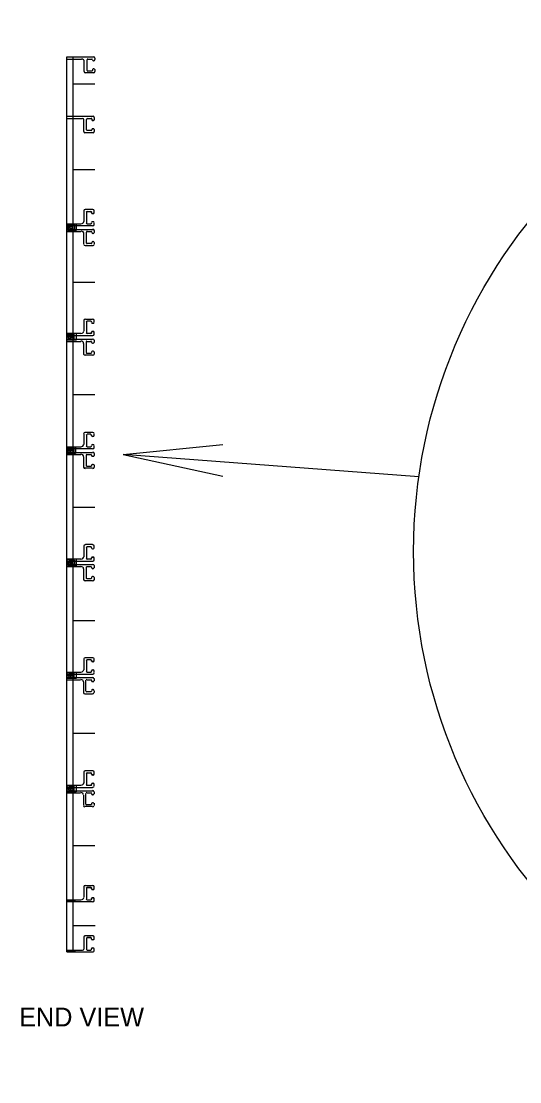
# Model space of a CAD drawing. Extents: x 647822 to 649292, y 298458 to 299646.
# Drawn here: x 648961.1 to 649074.6, y 299016.3 to 299257.7 of the extents above; entities that cross this region are included whole.
import ezdxf

# ---------------------------------------------------------------- set-up
doc = ezdxf.new("R2010")
doc.units = 0
doc.layers.add('2', color=7, linetype='Continuous')

msp = doc.modelspace()

# ---------------------------------------------------------------- linework, layer by layer
at = {"layer": '2'}
for p, q in [((648971.47, 299045.89), (648971.47, 299249.56)), ((648971.47, 299249.56), (648977.58, 299249.56)), ((648972.97, 299045.89), (648972.97, 299249.56)), ((648977.84, 299249.3), (648977.84, 299248.95)), ((648971.47, 299249.06), (648974.84, 299249.06)), ((648975.47, 299246.2), (648975.47, 299248.56)), ((648976.09, 299246.47), (648976.09, 299248.9)), ((648976.25, 299249.06), (648977.18, 299249.06)), ((648977.34, 299248.9), (648977.34, 299248.85)), ((648977.34, 299246.67), (648977.34, 299246.47)), ((648977.5, 299248.69), (648977.58, 299248.69)), ((648977.68, 299246.83), (648977.5, 299246.83)), ((648977.59, 299248.69), (648977.59, 299248.69)), ((648977.84, 299246.67), (648977.84, 299246.2)), ((648977.58, 299245.94), (648975.73, 299245.94)), ((648977.18, 299246.31), (648976.25, 299246.31)), ((648972.97, 299243.44), (648977.84, 299243.44)), ((648971.47, 299236.06), (648977.46, 299236.06)), ((648971.47, 299235.56), (648975.08, 299235.56)), ((648975.34, 299232.57), (648975.34, 299235.3)), ((648975.97, 299232.97), (648975.97, 299235.3)), ((648976.23, 299235.56), (648977.06, 299235.56)), ((648977.22, 299235.4), (648977.22, 299235.21)), ((648977.56, 299235.05), (648977.38, 299235.05)), ((648977.72, 299235.8), (648977.72, 299235.21)), ((648977.46, 299232.31), (648975.6, 299232.31)), ((648977.06, 299232.81), (648976.13, 299232.81)), ((648977.22, 299233.04), (648977.22, 299232.97)), ((648977.56, 299233.2), (648977.38, 299233.2)), ((648977.72, 299233.04), (648977.72, 299232.57)), ((648972.97, 299223.94), (648977.84, 299223.94)), ((648975.34, 299214.56), (648975.34, 299212.06)), ((648977.34, 299214.81), (648975.72, 299214.81)), ((648975.97, 299214.19), (648975.97, 299211.69)), ((648976.97, 299214.31), (648976.09, 299214.31)), ((648977.09, 299214.06), (648977.09, 299214.19)), ((648977.47, 299213.94), (648977.34, 299213.94)), ((648977.72, 299214.06), (648977.72, 299214.56)), ((648971.47, 299211.56), (648974.72, 299211.56)), ((648971.47, 299211.19), (648977.34, 299211.19)), ((648976.09, 299211.56), (648976.97, 299211.56)), ((648977.09, 299211.69), (648977.09, 299211.81)), ((648977.34, 299212.06), (648977.47, 299212.06)), ((648977.72, 299211.44), (648977.72, 299211.81)), ((648971.47, 299210.31), (648977.47, 299210.31)), ((648971.47, 299209.81), (648974.72, 299209.81)), ((648975.34, 299206.94), (648975.34, 299209.31)), ((648975.97, 299207.19), (648975.97, 299209.69)), ((648976.09, 299209.81), (648976.97, 299209.81)), ((648977.22, 299209.69), (648977.22, 299209.56)), ((648977.47, 299209.44), (648977.47, 299209.44)), ((648977.72, 299210.06), (648977.72, 299209.56)), ((648977.47, 299206.56), (648975.72, 299206.56)), ((648976.97, 299207.06), (648976.09, 299207.06)), ((648977.22, 299207.31), (648977.22, 299207.19)), ((648977.47, 299207.56), (648977.47, 299207.56)), ((648977.72, 299207.31), (648977.72, 299206.94)), ((648972.97, 299198.31), (648977.84, 299198.31)), ((648975.34, 299189.56), (648975.34, 299187.19)), ((648977.34, 299189.81), (648975.72, 299189.81)), ((648975.97, 299189.31), (648975.97, 299186.81)), ((648976.97, 299189.44), (648976.09, 299189.44)), ((648977.09, 299189.19), (648977.09, 299189.31)), ((648977.47, 299188.94), (648977.34, 299188.94)), ((648977.72, 299189.19), (648977.72, 299189.56)), ((648971.47, 299186.69), (648974.72, 299186.69)), ((648976.09, 299186.69), (648976.97, 299186.69)), ((648977.09, 299186.81), (648977.09, 299186.94)), ((648977.34, 299187.06), (648977.47, 299187.06)), ((648977.72, 299186.44), (648977.72, 299186.94)), ((648971.47, 299186.19), (648977.34, 299186.19)), ((648971.47, 299185.31), (648977.34, 299185.31)), ((648971.47, 299184.81), (648974.72, 299184.81)), ((648975.34, 299181.94), (648975.34, 299184.31)), ((648975.97, 299182.31), (648975.97, 299184.69)), ((648976.09, 299184.81), (648976.97, 299184.81)), ((648977.09, 299184.69), (648977.09, 299184.56)), ((648977.34, 299184.44), (648977.47, 299184.44)), ((648977.72, 299185.06), (648977.72, 299184.56)), ((648977.34, 299181.69), (648975.59, 299181.69)), ((648976.97, 299182.06), (648976.09, 299182.06)), ((648977.09, 299182.44), (648977.09, 299182.31)), ((648977.47, 299182.56), (648977.34, 299182.56)), ((648977.72, 299182.44), (648977.72, 299181.94)), ((648972.97, 299172.69), (648977.84, 299172.69)), ((648975.34, 299163.81), (648975.34, 299161.31)), ((648977.34, 299164.06), (648975.59, 299164.06)), ((648975.97, 299163.44), (648975.97, 299160.94)), ((648976.97, 299163.69), (648976.09, 299163.69)), ((648977.09, 299163.31), (648977.09, 299163.44)), ((648977.47, 299163.19), (648977.34, 299163.19)), ((648977.72, 299163.31), (648977.72, 299163.81)), ((648971.47, 299160.81), (648974.72, 299160.81)), ((648971.47, 299160.44), (648977.34, 299160.44)), ((648976.09, 299160.81), (648976.97, 299160.81)), ((648977.09, 299160.94), (648977.09, 299161.06)), ((648977.34, 299161.31), (648977.47, 299161.31)), ((648977.72, 299160.69), (648977.72, 299161.06)), ((648984.35, 299159.1), (649007, 299161.31)), ((648971.47, 299159.56), (648977.34, 299159.56)), ((648971.47, 299159.06), (648974.72, 299159.06)), ((648975.34, 299156.19), (648975.34, 299158.56)), ((648975.97, 299156.44), (648975.97, 299158.94)), ((648976.09, 299159.06), (648976.97, 299159.06)), ((648977.09, 299158.94), (648977.09, 299158.81)), ((648977.34, 299158.69), (648977.47, 299158.69)), ((648977.72, 299159.31), (648977.72, 299158.81)), ((649051.64, 299154.02), (648984.35, 299159.1)), ((648984.35, 299159.1), (649007, 299154.13)), ((648977.34, 299155.94), (648975.59, 299155.94)), ((648976.97, 299156.31), (648976.09, 299156.31)), ((648977.09, 299156.69), (648977.09, 299156.44)), ((648977.47, 299156.81), (648977.34, 299156.81)), ((648977.72, 299156.69), (648977.72, 299156.19)), ((648972.97, 299147.06), (648977.84, 299147.06)), ((648975.34, 299138.19), (648975.34, 299135.81)), ((648977.34, 299138.56), (648975.72, 299138.56)), ((648976.97, 299138.06), (648976.09, 299138.06)), ((648977.72, 299137.81), (648977.72, 299138.19)), ((648975.97, 299137.94), (648975.97, 299135.44)), ((648977.09, 299137.81), (648977.09, 299137.94)), ((648977.47, 299137.56), (648977.34, 299137.56)), ((648977.34, 299135.69), (648977.47, 299135.69)), ((648971.47, 299135.31), (648974.72, 299135.31)), ((648971.47, 299134.81), (648977.34, 299134.81)), ((648971.47, 299134.06), (648977.34, 299134.06)), ((648971.47, 299133.56), (648974.72, 299133.56)), ((648975.97, 299130.94), (648975.97, 299133.44)), ((648976.09, 299135.31), (648976.97, 299135.31)), ((648976.09, 299133.56), (648976.97, 299133.56)), ((648977.09, 299135.44), (648977.09, 299135.56)), ((648977.09, 299133.44), (648977.09, 299133.31)), ((648977.72, 299135.06), (648977.72, 299135.56)), ((648977.72, 299133.81), (648977.72, 299133.31)), ((648975.34, 299130.56), (648975.34, 299133.06)), ((648976.97, 299130.81), (648976.09, 299130.81)), ((648977.09, 299131.06), (648977.09, 299130.94)), ((648977.34, 299133.06), (648977.47, 299133.06)), ((648977.47, 299131.31), (648977.34, 299131.31)), ((648977.72, 299131.06), (648977.72, 299130.56)), ((648977.34, 299130.31), (648975.59, 299130.31)), ((648972.97, 299121.31), (648977.84, 299121.31)), ((648975.34, 299112.56), (648975.34, 299110.06)), ((648977.34, 299112.81), (648975.72, 299112.81)), ((648975.97, 299112.19), (648975.97, 299109.69)), ((648976.97, 299112.31), (648976.09, 299112.31)), ((648977.09, 299112.06), (648977.09, 299112.19)), ((648977.47, 299111.94), (648977.34, 299111.94)), ((648977.72, 299112.06), (648977.72, 299112.56)), ((648971.47, 299109.56), (648974.72, 299109.56)), ((648976.09, 299109.56), (648976.97, 299109.56)), ((648977.09, 299109.69), (648977.09, 299109.81)), ((648977.34, 299110.06), (648977.47, 299110.06)), ((648977.72, 299109.44), (648977.72, 299109.81)), ((648971.47, 299109.06), (648977.34, 299109.06)), ((648971.47, 299108.31), (648977.34, 299108.31)), ((648971.47, 299107.81), (648974.59, 299107.81)), ((648975.34, 299104.94), (648975.34, 299107.31)), ((648975.84, 299105.19), (648975.84, 299107.69)), ((648976.09, 299107.81), (648976.97, 299107.81)), ((648977.09, 299107.69), (648977.09, 299107.56)), ((648977.34, 299107.44), (648977.47, 299107.44)), ((648977.72, 299108.06), (648977.72, 299107.56)), ((648977.34, 299104.56), (648975.59, 299104.56)), ((648976.97, 299105.06), (648976.09, 299105.06)), ((648977.09, 299105.31), (648977.09, 299105.19)), ((648977.47, 299105.56), (648977.34, 299105.56)), ((648977.72, 299105.31), (648977.72, 299104.94)), ((648972.97, 299095.69), (648977.84, 299095.69)), ((648975.34, 299086.81), (648975.34, 299084.31)), ((648977.34, 299087.06), (648975.72, 299087.06)), ((648975.97, 299086.44), (648975.97, 299083.94)), ((648976.97, 299086.56), (648976.09, 299086.56)), ((648977.09, 299086.31), (648977.09, 299086.44)), ((648977.47, 299086.19), (648977.34, 299086.19)), ((648977.72, 299086.31), (648977.72, 299086.81)), ((648971.47, 299083.81), (648974.72, 299083.81)), ((648971.47, 299083.31), (648977.34, 299083.31)), ((648971.47, 299082.56), (648977.34, 299082.56)), ((648976.09, 299083.81), (648976.97, 299083.81)), ((648977.09, 299083.94), (648977.09, 299084.06)), ((648977.34, 299084.31), (648977.47, 299084.31)), ((648977.72, 299083.69), (648977.72, 299084.06)), ((648971.47, 299082.06), (648974.59, 299082.06)), ((648975.34, 299079.19), (648975.34, 299081.56)), ((648975.84, 299079.44), (648975.84, 299081.94)), ((648976.09, 299082.06), (648976.97, 299082.06)), ((648977.09, 299081.94), (648977.09, 299081.81)), ((648977.34, 299081.69), (648977.47, 299081.69)), ((648977.72, 299082.31), (648977.72, 299081.81)), ((648977.34, 299078.94), (648975.59, 299078.94)), ((648976.97, 299079.31), (648976.09, 299079.31)), ((648977.09, 299079.69), (648977.09, 299079.44)), ((648977.47, 299079.81), (648977.34, 299079.81)), ((648977.72, 299079.69), (648977.72, 299079.19)), ((648972.97, 299070.06), (648977.84, 299070.06)), ((648977.34, 299060.94), (648975.72, 299060.94)), ((648975.34, 299060.69), (648975.34, 299058.31)), ((648975.97, 299060.31), (648975.97, 299057.94)), ((648976.97, 299060.56), (648976.09, 299060.56)), ((648976.09, 299060.56), (648976.97, 299060.56)), ((648977.09, 299060.19), (648977.09, 299060.31)), ((648977.47, 299060.06), (648977.34, 299060.06)), ((648977.72, 299060.19), (648977.72, 299060.69)), ((648971.47, 299057.69), (648974.72, 299057.69)), ((648971.47, 299057.31), (648977.34, 299057.31)), ((648976.09, 299057.69), (648976.97, 299057.69)), ((648977.09, 299057.94), (648977.09, 299058.06)), ((648977.34, 299058.19), (648977.47, 299058.19)), ((648977.72, 299057.56), (648977.72, 299058.06)), ((648972.97, 299051.85), (648977.94, 299051.85)), ((648975.34, 299049.26), (648975.34, 299046.53)), ((648977.46, 299049.52), (648975.6, 299049.52)), ((648975.97, 299048.98), (648975.97, 299046.43)), ((648976.09, 299049.14), (648976.93, 299049.14)), ((648976.97, 299049.14), (648976.13, 299049.14)), ((648977.09, 299048.8), (648977.09, 299048.98)), ((648977.72, 299048.8), (648977.72, 299049.26)), ((648977.09, 299046.43), (648977.09, 299046.61)), ((648977.56, 299048.64), (648977.25, 299048.64)), ((648977.25, 299046.77), (648977.56, 299046.77)), ((648977.72, 299046.15), (648977.72, 299046.61)), ((648971.47, 299046.27), (648975.08, 299046.27)), ((648971.47, 299045.89), (648977.46, 299045.89)), ((648976.13, 299046.27), (648976.93, 299046.27))]:
    msp.add_line(p, q, dxfattribs=at)
for points in [[(648973.59, 299211.44), (648973.59, 299210.06), (648971.72, 299210.06), (648971.59, 299211.44), (648973.09, 299211.19), (648973.22, 299211.31), (648973.22, 299210.31), (648971.97, 299210.31), (648971.97, 299210.94), (648972.72, 299211.06), (648972.84, 299210.56), (648972.22, 299210.56), (648972.22, 299211.44), (648973.09, 299211.44), (648973.09, 299211.19)], [(648973.59, 299186.44), (648973.59, 299185.06), (648971.59, 299185.06), (648971.59, 299186.44), (648973.09, 299186.19), (648973.09, 299186.31), (648973.09, 299185.31), (648971.97, 299185.44), (648971.84, 299186.06), (648972.72, 299186.06), (648972.84, 299185.69), (648972.22, 299185.69), (648972.22, 299186.44), (648973.09, 299186.44), (648973.09, 299186.31)], [(648973.47, 299160.69), (648973.47, 299159.31), (648971.59, 299159.31), (648971.59, 299160.69), (648973.09, 299160.44), (648973.09, 299160.56), (648973.09, 299159.56), (648971.84, 299159.69), (648971.84, 299160.19), (648972.72, 299160.31), (648972.72, 299159.94), (648972.09, 299159.94), (648972.09, 299160.69), (648973.09, 299160.69), (648973.09, 299160.56)], [(648973.59, 299135.19), (648973.59, 299133.69), (648971.72, 299133.81), (648971.59, 299135.19), (648973.09, 299134.94), (648973.22, 299135.06), (648973.22, 299134.06), (648971.97, 299134.06), (648971.97, 299134.69), (648972.72, 299134.69), (648972.84, 299134.31), (648972.22, 299134.31), (648972.22, 299135.19), (648973.09, 299135.19), (648973.09, 299134.94)], [(648973.59, 299109.44), (648973.59, 299108.06), (648971.59, 299108.06), (648971.59, 299109.44), (648973.09, 299109.19), (648973.09, 299109.31), (648973.09, 299108.31), (648971.97, 299108.44), (648971.84, 299108.94), (648972.72, 299109.06), (648972.84, 299108.69), (648972.22, 299108.69), (648972.22, 299109.44), (648973.09, 299109.44), (648973.09, 299109.31)], [(648973.59, 299083.69), (648973.59, 299082.31), (648971.59, 299082.31), (648971.59, 299083.69), (648973.09, 299083.44), (648973.09, 299083.56), (648973.09, 299082.56), (648971.97, 299082.69), (648971.84, 299083.19), (648972.72, 299083.31), (648972.84, 299082.94), (648972.22, 299082.94), (648972.22, 299083.69), (648973.09, 299083.69), (648973.09, 299083.44)], [(648971.47, 299057.56), (648972.84, 299057.56), (648973.34, 299057.56), (648973.34, 299057.44), (648971.59, 299057.44)], [(648971.47, 299046.14), (648972.84, 299046.14), (648973.34, 299046.14), (648973.34, 299046.02), (648971.59, 299046.02)]]:
    msp.add_lwpolyline(points, dxfattribs=at)
msp.add_circle((649171.11, 299137), 120.68, dxfattribs=at)
for centre, radius, start, end in [((648977.58, 299249.3), 0.26, 0, 90), ((648976.25, 299248.9), 0.16, 90, 180), ((648977.18, 299248.9), 0.16, 0, 90), ((648977.5, 299248.85), 0.16, 180, 270), ((648977.5, 299246.67), 0.16, 90, 180), ((648977.58, 299248.95), 0.26, 270, 0), ((648977.68, 299246.67), 0.16, 0, 90), ((648975.73, 299246.2), 0.26, 180, 270), ((648976.25, 299246.47), 0.16, 180, 270), ((648977.18, 299246.47), 0.16, 270, 0), ((648977.58, 299246.2), 0.26, 270, 0), ((648975.08, 299235.3), 0.26, 0, 90), ((648976.23, 299235.3), 0.26, 90, 180), ((648977.06, 299235.4), 0.16, 0, 90), ((648977.38, 299235.21), 0.16, 180, 270), ((648977.46, 299235.8), 0.26, 0, 90), ((648977.56, 299235.21), 0.16, 270, 0), ((648975.6, 299232.57), 0.26, 180, 270), ((648976.13, 299232.97), 0.16, 180, 270), ((648977.06, 299232.97), 0.16, 270, 0), ((648977.38, 299233.04), 0.16, 90, 180), ((648977.46, 299232.57), 0.26, 270, 0), ((648977.56, 299233.04), 0.16, 0, 90), ((648975.6, 299049.26), 0.26, 90, 180), ((648976.13, 299048.98), 0.16, 90, 180), ((648976.93, 299048.98), 0.16, 0, 90), ((648977.25, 299048.8), 0.16, 180, 270), ((648977.46, 299049.26), 0.26, 0, 90), ((648977.56, 299048.8), 0.16, 270, 0), ((648975.08, 299046.53), 0.26, 270, 0), ((648976.13, 299046.43), 0.16, 180, 270), ((648976.93, 299046.43), 0.16, 270, 0), ((648977.25, 299046.61), 0.16, 90, 180), ((648977.56, 299046.61), 0.16, 0, 90), ((648977.46, 299046.15), 0.26, 270, 0)]:
    msp.add_arc(centre, radius, start, end, dxfattribs=at)
for centre, major_axis, start_param, end_param in [((648974.82, 299248.54), (0.653, 0), 0, 1.570796), ((648975.68, 299214.55), (-0.327, 0), 4.712389, 6.283185), ((648976.09, 299214.22), (-0.163, 0), 4.712389, 6.283185), ((648976.99, 299214.22), (-0.163, 0), 3.141593, 4.712389), ((648977.4, 299214.09), (0.251, 0), 3.141593, 4.712389), ((648977.4, 299214.55), (0.327, 0), 0, 1.570796), ((648977.48, 299214.09), (0.251, 0), 4.712389, 6.283185), ((648974.7, 299212.11), (0.653, 0), 4.712389, 6.283185), ((648976.09, 299211.71), (0.163, 0), 3.141593, 4.712389), ((648976.99, 299211.71), (0.163, 0), 4.712389, 6.283185), ((648977.4, 299211.84), (-0.251, 0), 4.712389, 6.283185), ((648977.4, 299211.39), (0.327, 0), 4.712389, 6.283185), ((648977.48, 299211.84), (0.251, 0), 0, 1.570796), ((648974.73, 299209.34), (0.653, 0), 0, 1.570796), ((648976.11, 299209.73), (-0.163, 0), 4.712389, 6.283185), ((648977.01, 299209.73), (0.163, 0), 0, 1.570796), ((648977.43, 299209.6), (-0.251, 0), 0, 1.570796), ((648977.43, 299210.06), (0.327, 0), 0, 1.570796), ((648977.5, 299209.6), (0.251, 0), 4.712389, 6.283185), ((648975.7, 299206.89), (0.327, 0), 3.141593, 4.712389), ((648976.11, 299207.22), (-0.163, 0), 0, 1.570796), ((648977.01, 299207.22), (0.163, 0), 4.712389, 6.283185), ((648977.43, 299207.35), (-0.251, 0), 4.712389, 6.283185), ((648977.43, 299206.89), (0.327, 0), 4.712389, 6.283185), ((648977.5, 299207.35), (-0.251, 0), 3.141593, 4.712389), ((648975.68, 299189.6), (-0.327, 0), 4.712389, 6.283185), ((648976.09, 299189.27), (-0.163, 0), 4.712389, 6.283185), ((648976.99, 299189.27), (-0.163, 0), 3.141593, 4.712389), ((648977.4, 299189.14), (0.251, 0), 3.141593, 4.712389), ((648977.4, 299189.6), (0.327, 0), 0, 1.570796), ((648977.48, 299189.14), (0.251, 0), 4.712389, 6.283185), ((648974.7, 299187.15), (0.653, 0), 4.712389, 6.283185), ((648976.09, 299186.76), (0.163, 0), 3.141593, 4.712389), ((648976.99, 299186.76), (0.163, 0), 4.712389, 6.283185), ((648977.4, 299186.89), (-0.251, 0), 4.712389, 6.283185), ((648977.4, 299186.43), (0.327, 0), 4.712389, 6.283185), ((648977.48, 299186.89), (0.251, 0), 0, 1.570796), ((648974.67, 299184.35), (0.653, 0), 0, 1.570796), ((648976.06, 299184.75), (-0.163, 0), 4.712389, 6.283185), ((648976.96, 299184.75), (0.163, 0), 0, 1.570796), ((648977.38, 299184.62), (-0.251, 0), 0, 1.570796), ((648977.38, 299185.08), (0.327, 0), 0, 1.570796), ((648977.45, 299184.62), (0.251, 0), 4.712389, 6.283185), ((648975.65, 299181.91), (0.327, 0), 3.141593, 4.712389), ((648976.06, 299182.24), (-0.163, 0), 0, 1.570796), ((648976.96, 299182.24), (0.163, 0), 4.712389, 6.283185), ((648977.38, 299182.37), (-0.251, 0), 4.712389, 6.283185), ((648977.38, 299181.91), (0.327, 0), 4.712389, 6.283185), ((648977.45, 299182.37), (-0.251, 0), 3.141593, 4.712389), ((648975.65, 299163.82), (-0.327, 0), 4.712389, 6.283185), ((648976.06, 299163.49), (-0.163, 0), 4.712389, 6.283185), ((648976.96, 299163.49), (-0.163, 0), 3.141593, 4.712389), ((648977.38, 299163.36), (0.251, 0), 3.141593, 4.712389), ((648977.38, 299163.82), (0.327, 0), 0, 1.570796), ((648977.45, 299163.36), (0.251, 0), 4.712389, 6.283185), ((648974.67, 299161.37), (0.653, 0), 4.712389, 6.283185), ((648976.06, 299160.98), (0.163, 0), 3.141593, 4.712389), ((648976.96, 299160.98), (0.163, 0), 4.712389, 6.283185), ((648977.38, 299161.11), (-0.251, 0), 4.712389, 6.283185), ((648977.38, 299160.65), (0.327, 0), 4.712389, 6.283185), ((648977.45, 299161.11), (0.251, 0), 0, 1.570796), ((648974.67, 299158.6), (0.653, 0), 0, 1.570796), ((648976.06, 299158.99), (-0.163, 0), 4.712389, 6.283185), ((648976.96, 299158.99), (0.163, 0), 0, 1.570796), ((648977.38, 299158.86), (-0.251, 0), 0, 1.570796), ((648977.38, 299159.32), (0.327, 0), 0, 1.570796), ((648977.45, 299158.86), (0.251, 0), 4.712389, 6.283185), ((648975.65, 299156.16), (0.327, 0), 3.141593, 4.712389), ((648976.06, 299156.49), (-0.163, 0), 0, 1.570796), ((648976.96, 299156.49), (0.163, 0), 4.712389, 6.283185), ((648977.38, 299156.61), (-0.251, 0), 4.712389, 6.283185), ((648977.38, 299156.16), (0.327, 0), 4.712389, 6.283185), ((648977.45, 299156.61), (-0.251, 0), 3.141593, 4.712389), ((648975.68, 299138.24), (-0.327, 0), 4.712389, 6.283185), ((648976.09, 299137.91), (-0.163, 0), 4.712389, 6.283185), ((648976.99, 299137.91), (-0.163, 0), 3.141593, 4.712389), ((648977.4, 299138.24), (0.327, 0), 0, 1.570796), ((648974.7, 299135.8), (0.653, 0), 4.712389, 6.283185), ((648977.4, 299137.79), (0.251, 0), 3.141593, 4.712389), ((648977.4, 299135.54), (-0.251, 0), 4.712389, 6.283185), ((648977.48, 299137.79), (0.251, 0), 4.712389, 6.283185), ((648977.48, 299135.54), (0.251, 0), 0, 1.570796), ((648974.67, 299133.05), (0.653, 0), 0, 1.570796), ((648976.06, 299133.45), (-0.163, 0), 4.712389, 6.283185), ((648976.09, 299135.41), (0.163, 0), 3.141593, 4.712389), ((648976.96, 299133.45), (0.163, 0), 0, 1.570796), ((648976.99, 299135.41), (0.163, 0), 4.712389, 6.283185), ((648977.38, 299133.32), (-0.251, 0), 0, 1.570796), ((648977.38, 299133.78), (0.327, 0), 0, 1.570796), ((648977.4, 299135.08), (0.327, 0), 4.712389, 6.283185), ((648977.45, 299133.32), (0.251, 0), 4.712389, 6.283185), ((648976.06, 299130.94), (-0.163, 0), 0, 1.570796), ((648976.96, 299130.94), (0.163, 0), 4.712389, 6.283185), ((648977.38, 299131.07), (-0.251, 0), 4.712389, 6.283185), ((648977.45, 299131.07), (-0.251, 0), 3.141593, 4.712389), ((648975.65, 299130.61), (0.327, 0), 3.141593, 4.712389), ((648977.38, 299130.61), (0.327, 0), 4.712389, 6.283185), ((648975.68, 299112.54), (-0.327, 0), 4.712389, 6.283185), ((648976.09, 299112.21), (-0.163, 0), 4.712389, 6.283185), ((648976.99, 299112.21), (-0.163, 0), 3.141593, 4.712389), ((648977.4, 299112.08), (0.251, 0), 3.141593, 4.712389), ((648977.4, 299112.54), (0.327, 0), 0, 1.570796), ((648977.48, 299112.08), (0.251, 0), 4.712389, 6.283185), ((648974.7, 299110.1), (0.653, 0), 4.712389, 6.283185), ((648976.09, 299109.7), (0.163, 0), 3.141593, 4.712389), ((648976.99, 299109.7), (0.163, 0), 4.712389, 6.283185), ((648977.4, 299109.83), (-0.251, 0), 4.712389, 6.283185), ((648977.4, 299109.38), (0.327, 0), 4.712389, 6.283185), ((648977.48, 299109.83), (0.251, 0), 0, 1.570796), ((648974.65, 299107.33), (0.653, 0), 0, 1.570796), ((648976.04, 299107.72), (-0.163, 0), 4.712389, 6.283185), ((648976.94, 299107.72), (0.163, 0), 0, 1.570796), ((648977.35, 299107.59), (-0.251, 0), 0, 1.570796), ((648977.35, 299108.05), (0.327, 0), 0, 1.570796), ((648977.43, 299107.59), (0.251, 0), 4.712389, 6.283185), ((648975.63, 299104.88), (0.327, 0), 3.141593, 4.712389), ((648976.04, 299105.21), (-0.163, 0), 0, 1.570796), ((648976.94, 299105.21), (0.163, 0), 4.712389, 6.283185), ((648977.35, 299105.34), (-0.251, 0), 4.712389, 6.283185), ((648977.35, 299104.88), (0.327, 0), 4.712389, 6.283185), ((648977.43, 299105.34), (-0.251, 0), 3.141593, 4.712389), ((648975.68, 299086.79), (-0.327, 0), 4.712389, 6.283185), ((648976.09, 299086.46), (-0.163, 0), 4.712389, 6.283185), ((648976.99, 299086.46), (-0.163, 0), 3.141593, 4.712389), ((648977.4, 299086.33), (0.251, 0), 3.141593, 4.712389), ((648977.4, 299086.79), (0.327, 0), 0, 1.570796), ((648977.48, 299086.33), (0.251, 0), 4.712389, 6.283185), ((648974.7, 299084.35), (0.653, 0), 4.712389, 6.283185), ((648976.09, 299083.95), (0.163, 0), 3.141593, 4.712389), ((648976.99, 299083.95), (0.163, 0), 4.712389, 6.283185), ((648977.4, 299084.08), (-0.251, 0), 4.712389, 6.283185), ((648977.35, 299082.32), (0.327, 0), 0, 1.570796), ((648977.4, 299083.62), (0.327, 0), 4.712389, 6.283185), ((648977.48, 299084.08), (0.251, 0), 0, 1.570796), ((648974.65, 299081.6), (0.653, 0), 0, 1.570796), ((648976.04, 299081.99), (-0.163, 0), 4.712389, 6.283185), ((648976.94, 299081.99), (0.163, 0), 0, 1.570796), ((648977.35, 299081.86), (-0.251, 0), 0, 1.570796), ((648977.43, 299081.86), (0.251, 0), 4.712389, 6.283185), ((648975.63, 299079.15), (0.327, 0), 3.141593, 4.712389), ((648976.04, 299079.49), (-0.163, 0), 0, 1.570796), ((648976.94, 299079.49), (0.163, 0), 4.712389, 6.283185), ((648977.35, 299079.61), (-0.251, 0), 4.712389, 6.283185), ((648977.35, 299079.15), (0.327, 0), 4.712389, 6.283185), ((648977.43, 299079.61), (-0.251, 0), 3.141593, 4.712389), ((648975.68, 299060.7), (-0.327, 0), 4.712389, 6.283185), ((648977.4, 299060.7), (0.327, 0), 0, 1.570796), ((648976.09, 299060.37), (-0.163, 0), 4.712389, 6.283185), ((648976.99, 299060.37), (-0.163, 0), 3.141593, 4.712389), ((648977.4, 299060.25), (0.251, 0), 3.141593, 4.712389), ((648977.48, 299060.25), (0.251, 0), 4.712389, 6.283185), ((648974.7, 299058.26), (0.653, 0), 4.712389, 6.283185), ((648976.09, 299057.87), (0.163, 0), 3.141593, 4.712389), ((648976.99, 299057.87), (0.163, 0), 4.712389, 6.283185), ((648977.4, 299058), (-0.251, 0), 4.712389, 6.283185), ((648977.4, 299057.54), (0.327, 0), 4.712389, 6.283185), ((648977.48, 299058), (0.251, 0), 0, 1.570796)]:
    msp.add_ellipse(centre, major_axis=major_axis, ratio=0.806863, start_param=start_param, end_param=end_param, dxfattribs=at)

# ---------------------------------------------------------------- texts
msp.add_text('END VIEW', height=4.3, dxfattribs=at).set_placement((648960.64, 299028.9))

doc.saveas('drawing.dxf')
